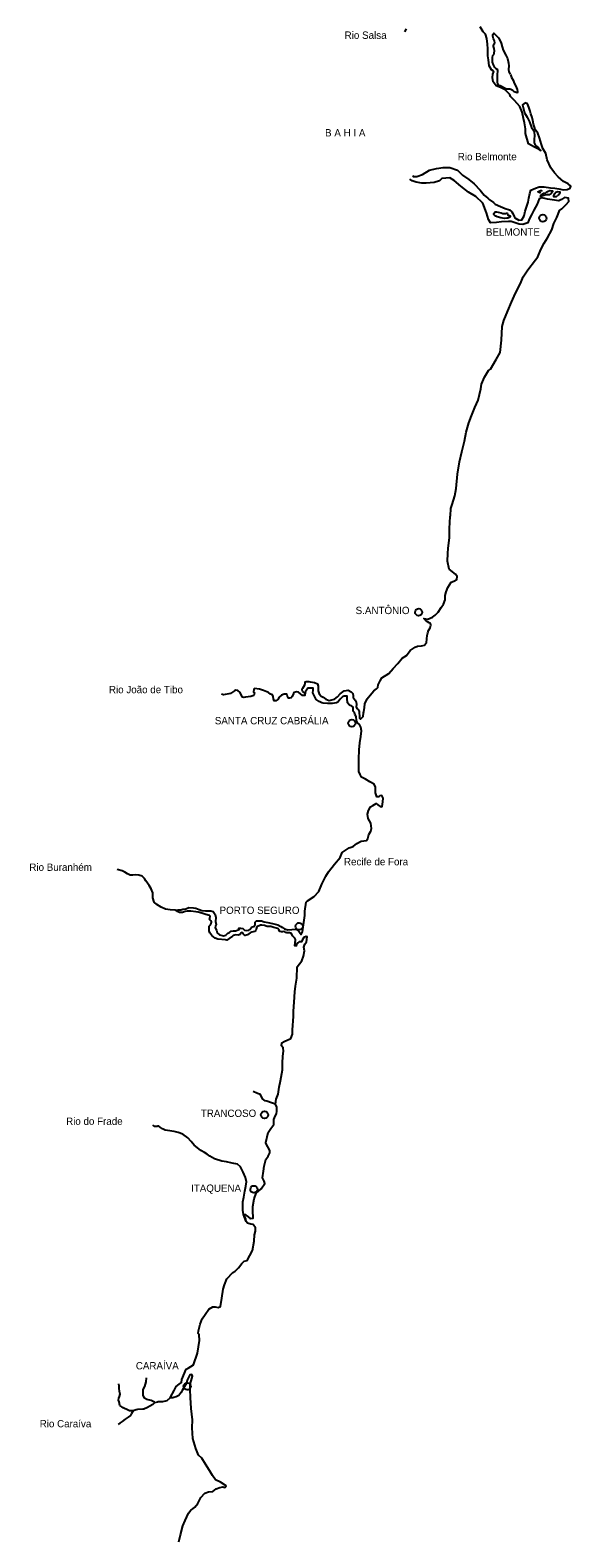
# Model space of a CAD drawing. Extents: x 662444 to 1640468, y 7452018 to 9606170.
# Drawn here: x 1109656 to 1158304, y 8117861 to 8253447 of the extents above; entities that cross this region are included whole.
import ezdxf

# ---------------------------------------------------------------- set-up
doc = ezdxf.new("R2010")
doc.units = 0
for name, color, linetype in [('Level 1', 7, 'Continuous'), ('Level 2', 7, 'Continuous'), ('Level 3', 7, 'Continuous')]:
    doc.layers.add(name, color=color, linetype=linetype)

msp = doc.modelspace()

# ---------------------------------------------------------------- linework, layer by layer
at = {"layer": 'Level 1'}
msp.add_line((1129077, 8146318), (1128864, 8146948), dxfattribs=at)
for points in [[(1143491, 8253560), (1143322, 8253309)], [(1151324, 8249799), (1151165, 8249881), (1150959, 8250243), (1150900, 8250790), (1150845, 8251125), (1150843, 8251437), (1150820, 8251760), (1150800, 8252194), (1150750, 8252685), (1150610, 8253079), (1150423, 8253307), (1150144, 8253737)], [(1152866, 8249465), (1152976, 8249184), (1153109, 8248946), (1153209, 8248676), (1153341, 8248406), (1153402, 8248259), (1153472, 8248101), (1153500, 8247945), (1153498, 8247867), (1153464, 8247824), (1153208, 8247898), (1153072, 8248024), (1152912, 8248106), (1152806, 8248154), (1152730, 8248145), (1152687, 8248146), (1152526, 8248151), (1152345, 8248245), (1152133, 8248352), (1151931, 8248435), (1151823, 8248438), (1151731, 8248597), (1151693, 8248787), (1151701, 8249054), (1151707, 8249254), (1151713, 8249487), (1151720, 8249721), (1151725, 8249876), (1151576, 8249970), (1151451, 8250084), (1151339, 8250321), (1151260, 8250579), (1151255, 8250780), (1151261, 8250980), (1151277, 8251157), (1151365, 8251244), (1151413, 8251387), (1151419, 8251598), (1151403, 8251810), (1151354, 8251967), (1151357, 8252078), (1151370, 8252134), (1151416, 8252232), (1151450, 8252309), (1151444, 8252487), (1151353, 8252668), (1151284, 8252892), (1151278, 8253071), (1151367, 8253179), (1151807, 8252744), (1152002, 8252382), (1152031, 8252270), (1152129, 8251956), (1152228, 8251653), (1152452, 8251201), (1152605, 8250896), (1152662, 8250628), (1152690, 8250482), (1152716, 8250248), (1152706, 8249915), (1152732, 8249691), (1152834, 8249499)], [(1144073, 8240363), (1144113, 8240284), (1144448, 8240297), (1144948, 8240461), (1145594, 8240854), (1146223, 8241002), (1146829, 8241096), (1147421, 8241090), (1148114, 8240848), (1148543, 8240402), (1149124, 8240007), (1149597, 8239637), (1150140, 8239054), (1150516, 8238620), (1150820, 8238333), (1150956, 8238207), (1151336, 8237940), (1151482, 8237802), (1151961, 8237577), (1152408, 8237408), (1152770, 8237287), (1153002, 8237113), (1153095, 8236954), (1153194, 8236685), (1153266, 8236560), (1153637, 8236371), (1153896, 8236386), (1154090, 8236747), (1154188, 8237167), (1154352, 8237619), (1154460, 8237971), (1154514, 8238348), (1154601, 8238746), (1154717, 8239043), (1155132, 8239231), (1155448, 8239367), (1155900, 8239353), (1156479, 8239281), (1156865, 8239225), (1157230, 8239170), (1157637, 8239080), (1157972, 8239126), (1158234, 8239252), (1158304, 8239416), (1158062, 8239613), (1157638, 8239848), (1157165, 8240262), (1156820, 8240617), (1156488, 8241061), (1156186, 8241781), (1156063, 8242341), (1155774, 8242795), (1155667, 8243165), (1155468, 8243749), (1155319, 8244176), (1155103, 8244516), (1155044, 8244729), (1154955, 8244988), (1154889, 8245312), (1154833, 8245603), (1154702, 8245919), (1154633, 8246154), (1154536, 8246513), (1154416, 8246817), (1154192, 8246924), (1153939, 8246720), (1154145, 8246024), (1154381, 8245616), (1154574, 8245210), (1154774, 8244693), (1154980, 8244386), (1155000, 8244308), (1155032, 8243940), (1155013, 8243651), (1155004, 8243329), (1155075, 8243182), (1155220, 8243011), (1155388, 8242850), (1155555, 8242656), (1155597, 8242611), (1155215, 8242833), (1155024, 8242917), (1154505, 8243221), (1154220, 8244164), (1154232, 8244586), (1154119, 8245123), (1154055, 8245515), (1153931, 8246075), (1153698, 8246582), (1153229, 8247118), (1152873, 8247485), (1152825, 8247675), (1152552, 8247928), (1152383, 8248066), (1151959, 8248279), (1151586, 8248434), (1151306, 8248798), (1151241, 8249178), (1151293, 8249488), (1151365, 8249720), (1151324, 8249799)], [(1156945, 8236419), (1157036, 8236594), (1157164, 8236902), (1157291, 8237221), (1157500, 8237371), (1157711, 8237576), (1157878, 8237771), (1158123, 8238031), (1158089, 8238344), (1157746, 8238409), (1157471, 8238206), (1157209, 8238091), (1156609, 8238187), (1156201, 8238243), (1156084, 8238269), (1155699, 8238369), (1155448, 8238276), (1155262, 8237803), (1154977, 8237244), (1154760, 8236828), (1154566, 8236444), (1154438, 8236114), (1153981, 8235972), (1153638, 8236004), (1152944, 8236225), (1152697, 8236232), (1152061, 8236206), (1151628, 8236152), (1151068, 8236124), (1150882, 8236407), (1150727, 8237012), (1150397, 8237878), (1149747, 8238476), (1149080, 8238884), (1148395, 8239405), (1147807, 8239922), (1147427, 8240167), (1146692, 8240099), (1146482, 8239905), (1145993, 8239741), (1145280, 8239673), (1144882, 8239684), (1144379, 8239776), (1144027, 8239909), (1143806, 8240060)], [(1155606, 8238861), (1155508, 8238831), (1155443, 8238833), (1155338, 8238903), (1155382, 8238946), (1155513, 8239009), (1155578, 8239018), (1155632, 8239027), (1155653, 8239016), (1155618, 8238905)], [(1156100, 8238814), (1156156, 8238901), (1156255, 8238976), (1156397, 8239027), (1156568, 8239000), (1156643, 8238987), (1156641, 8238909), (1156518, 8238757), (1156342, 8238651), (1156148, 8238645), (1155954, 8238618), (1155779, 8238545), (1155703, 8238514), (1155574, 8238506), (1155542, 8238529), (1155642, 8238627), (1155752, 8238701), (1155861, 8238776), (1156078, 8238814)], [(1157039, 8238530), (1156940, 8238444), (1156757, 8238449), (1156760, 8238572), (1156852, 8238758), (1156963, 8238877), (1157137, 8238928), (1157298, 8238912), (1157307, 8238856), (1157292, 8238712), (1157215, 8238658), (1157083, 8238562)], [(1151686, 8236651), (1151559, 8236721), (1151443, 8236813), (1151380, 8236882), (1151383, 8236971), (1151484, 8237101), (1151623, 8237097), (1151763, 8237093), (1152041, 8237019), (1152190, 8236970), (1152330, 8236966), (1152427, 8236963), (1152514, 8236982), (1152578, 8236981), (1152598, 8236924), (1152638, 8236823), (1152703, 8236810), (1152777, 8236775), (1152852, 8236761), (1152849, 8236661), (1152750, 8236586), (1152630, 8236545), (1152555, 8236547), (1152325, 8236514), (1152009, 8236567), (1151686, 8236651)], [(1139251, 8192075), (1139284, 8191729), (1139280, 8191585), (1139384, 8191470), (1139607, 8191731), (1139637, 8192041), (1139673, 8192152), (1139737, 8192528), (1139779, 8192849), (1139964, 8193300), (1140410, 8193832), (1140587, 8194027), (1140829, 8194209), (1140929, 8194328), (1140979, 8194571), (1141141, 8194945), (1141288, 8195196), (1141922, 8195578), (1142323, 8196045), (1142723, 8196489), (1143124, 8196967), (1143507, 8197200), (1143832, 8197658), (1144282, 8197967), (1144510, 8198060), (1144877, 8198094), (1145146, 8198131), (1145214, 8198251), (1145304, 8198360), (1145335, 8198703), (1145387, 8199002), (1145426, 8199235), (1145508, 8199466), (1145644, 8199696), (1145704, 8199927), (1145666, 8200073), (1145561, 8200154), (1145413, 8200247), (1145223, 8200375), (1145088, 8200524), (1145249, 8200519), (1145431, 8200480), (1145855, 8200657), (1146097, 8200850), (1146352, 8201121), (1146622, 8201524), (1146835, 8201830), (1146987, 8202214), (1146998, 8202603), (1147073, 8202946), (1147224, 8203331), (1147539, 8203800), (1147778, 8203904), (1148051, 8204052), (1148070, 8204329), (1147925, 8204512), (1147347, 8204963), (1147207, 8205690), (1147249, 8206378), (1147263, 8206856), (1147398, 8207787), (1147390, 8208621), (1147455, 8209709), (1147489, 8209775), (1147519, 8210430), (1147626, 8210794), (1147864, 8211555), (1147991, 8212219), (1148104, 8213528), (1148298, 8214612), (1148497, 8215530), (1148740, 8216491), (1148882, 8217299), (1149111, 8218126), (1149377, 8218764), (1149668, 8219523), (1149977, 8220170), (1150212, 8221197), (1150267, 8221619), (1150533, 8222245), (1150906, 8222846), (1151071, 8222974), (1151570, 8223839), (1151933, 8224462), (1152062, 8225582), (1152109, 8226793), (1152286, 8227333), (1152623, 8228191), (1152969, 8228982), (1153337, 8229794), (1153761, 8230661), (1154026, 8231254), (1154422, 8231887), (1155126, 8232790), (1155339, 8233073), (1155616, 8233710), (1155902, 8234291), (1156196, 8234761), (1156605, 8235483), (1156762, 8236046), (1156945, 8236419)], [(1138973, 8191738), (1138861, 8191942), (1138833, 8192087), (1138812, 8192110), (1138760, 8192167), (1138728, 8192190), (1138710, 8192291), (1138715, 8192458), (1138707, 8192569), (1138613, 8192650), (1138380, 8192757), (1138203, 8192962), (1138171, 8193341), (1138177, 8193541), (1138081, 8193555), (1137973, 8193558), (1137909, 8193549), (1137767, 8193486), (1137547, 8193293), (1137324, 8193021), (1137214, 8192958), (1136858, 8192879), (1136407, 8192892), (1136032, 8192936), (1135893, 8192952), (1135649, 8193059), (1135397, 8193266), (1135233, 8193549), (1135103, 8193853), (1135109, 8194087), (1135115, 8194276), (1135050, 8194277), (1134879, 8194282), (1134653, 8194267), (1134508, 8194104), (1134419, 8193984), (1134402, 8193796), (1134161, 8193992), (1134122, 8194126), (1134124, 8194204), (1134180, 8194281), (1134382, 8194575), (1134387, 8194731), (1134401, 8194852), (1134477, 8194872), (1134724, 8194865), (1134852, 8194828), (1135055, 8194800), (1135248, 8194794), (1135513, 8194653), (1135582, 8194462), (1135576, 8194262), (1135570, 8194029), (1135659, 8193770), (1135835, 8193565), (1136015, 8193449), (1136257, 8193275), (1136555, 8193177), (1137042, 8193296), (1137316, 8193500), (1137550, 8193771), (1137923, 8194027), (1138257, 8194084), (1138543, 8193931), (1138690, 8193804), (1138715, 8193581), (1138733, 8193447), (1138909, 8193208), (1139000, 8193017), (1139005, 8192816), (1138998, 8192605), (1139036, 8192437), (1139205, 8192332), (1139267, 8192230), (1139251, 8192075)], [(1134402, 8193796), (1134379, 8193730), (1134365, 8193619), (1134161, 8193614), (1133983, 8193764), (1133804, 8193902), (1133633, 8193929), (1133417, 8193891), (1133350, 8193793), (1133234, 8193529), (1133134, 8193399), (1132983, 8193370), (1132886, 8193373), (1132786, 8193609), (1132746, 8193722), (1132510, 8193728), (1132271, 8193635), (1132051, 8193464), (1131937, 8193245), (1131762, 8193138), (1131622, 8193142), (1131541, 8193301), (1131526, 8193523), (1131455, 8193670), (1131285, 8193719), (1131107, 8193891), (1130661, 8194060), (1130277, 8194182), (1129838, 8194228), (1129783, 8194185), (1129754, 8193919), (1129827, 8193839), (1129767, 8193608), (1129518, 8193537), (1129043, 8193473), (1128881, 8193444), (1128753, 8193470), (1128610, 8193741), (1128550, 8193876), (1128351, 8194060), (1128148, 8194088), (1128039, 8194047), (1127688, 8193790), (1127040, 8193675), (1126870, 8193724)], [(1133192, 8172566), (1133547, 8172612), (1133821, 8172426), (1133882, 8172335), (1134037, 8172119), (1134162, 8172349), (1134367, 8173833), (1134378, 8174233), (1134477, 8175031), (1134620, 8175138), (1135200, 8175533), (1135632, 8175976), (1135899, 8176658), (1136263, 8177359), (1136500, 8177741), (1137047, 8178459), (1137537, 8179056), (1137743, 8179484), (1138346, 8179900), (1138704, 8180023), (1139045, 8180291), (1139438, 8180524), (1139912, 8180577), (1140046, 8180740), (1140121, 8181105), (1140302, 8181411), (1140363, 8181665), (1140301, 8182123), (1140067, 8182563), (1140014, 8182943), (1140110, 8183274), (1140270, 8183592), (1140488, 8183708), (1140773, 8183899), (1140941, 8183772), (1141141, 8183633), (1141290, 8183595), (1141323, 8183638), (1141378, 8184037), (1141421, 8184381), (1141309, 8184607), (1141115, 8184579), (1141027, 8184504), (1140855, 8184498), (1140726, 8184857), (1140740, 8185357), (1140609, 8185639), (1140207, 8185840), (1139817, 8186085), (1139479, 8186273), (1139346, 8186511), (1139214, 8186782), (1139220, 8187360), (1139236, 8187882), (1139260, 8188716), (1139322, 8189370), (1139414, 8189912), (1139461, 8190423), (1139396, 8190780), (1139274, 8191018), (1139117, 8191167), (1139026, 8191359), (1138973, 8191738)], [(1122745, 8174294), (1122243, 8174353), (1121836, 8174387), (1121455, 8174587), (1121043, 8174810), (1120824, 8175039), (1120707, 8175420), (1120687, 8175854), (1120558, 8176236), (1120352, 8176520), (1120053, 8176940), (1119951, 8177143), (1119743, 8177360), (1119434, 8177469), (1119145, 8177478), (1118897, 8177451), (1118651, 8177458), (1118428, 8177565), (1118186, 8177739), (1117932, 8177857), (1117484, 8177959)], [(1129827, 8172398), (1129611, 8172338), (1129459, 8172275), (1129206, 8172083), (1129012, 8172044), (1128906, 8172080), (1128823, 8172172), (1128794, 8172284), (1128686, 8172287), (1128632, 8172255), (1128553, 8172135), (1128542, 8172124), (1128380, 8172073), (1128176, 8172079), (1127928, 8172031), (1127851, 8171966), (1127566, 8171775), (1127347, 8171625), (1127218, 8171629), (1126544, 8171693), (1126311, 8171800), (1126017, 8172020), (1125832, 8172281), (1125761, 8172450), (1125768, 8172672), (1125773, 8172861), (1125874, 8173003), (1125953, 8173123), (1125967, 8173244), (1125916, 8173335), (1125791, 8173483), (1125837, 8173571), (1125842, 8173760), (1125801, 8173828), (1125460, 8173915), (1125110, 8174037), (1124769, 8174124), (1124577, 8174163), (1124106, 8174221), (1123785, 8174231), (1123612, 8174202), (1123362, 8174087), (1123083, 8174095), (1122914, 8174200), (1122745, 8174294), (1122972, 8174332), (1123218, 8174325), (1123403, 8174386), (1123651, 8174435), (1123933, 8174538), (1124362, 8174525), (1124565, 8174486), (1124861, 8174355), (1125106, 8174281), (1125438, 8174261), (1125910, 8174247), (1126133, 8174174), (1126298, 8173924), (1126354, 8173656), (1126343, 8173278), (1126379, 8173032), (1126343, 8172900), (1126306, 8172734), (1126418, 8172509), (1126497, 8172273), (1126696, 8172100), (1127047, 8172012), (1127263, 8172061), (1127429, 8172234), (1127582, 8172308), (1127746, 8172414), (1127940, 8172453), (1128144, 8172458), (1128459, 8172571), (1128428, 8172639), (1128419, 8172684), (1128612, 8172678), (1128805, 8172673), (1128888, 8172581), (1128950, 8172502), (1129132, 8172474), (1129326, 8172502), (1129435, 8172576), (1129580, 8172761), (1129667, 8172803), (1129841, 8172865), (1129898, 8172985), (1129902, 8173108), (1129916, 8173218), (1130026, 8173338), (1130295, 8173341), (1130466, 8173336), (1130722, 8173273), (1131042, 8173186), (1131447, 8173096), (1131927, 8172982), (1132223, 8172840), (1132349, 8172758), (1132528, 8172619), (1132826, 8172533), (1133192, 8172566)], [(1129077, 8146318), (1129057, 8146511), (1128940, 8146812), (1128915, 8146946), (1129035, 8146931), (1129161, 8146828), (1129411, 8146598), (1129507, 8146573), (1129712, 8146622), (1129679, 8147313), (1129690, 8147668), (1129817, 8148343), (1130003, 8148849), (1130434, 8149259), (1130769, 8149716), (1130722, 8149929), (1130559, 8150223), (1130641, 8150832), (1130708, 8151297), (1130865, 8151893), (1131067, 8152176), (1131216, 8152494), (1131222, 8152694), (1130866, 8153350), (1130847, 8153428), (1131066, 8154312), (1131301, 8154661), (1131581, 8155042), (1131593, 8155475), (1131710, 8155794), (1131824, 8156002), (1131852, 8156235), (1131841, 8156580), (1131731, 8156850), (1131787, 8157315), (1131972, 8157766), (1132055, 8158386), (1132190, 8158961), (1132359, 8159957), (1132365, 8160535), (1132384, 8161168), (1132440, 8161634), (1132406, 8161935), (1132282, 8162094), (1132291, 8162372), (1132509, 8162488), (1133117, 8162759), (1133258, 8163144), (1133269, 8163544), (1133337, 8164743), (1133362, 8165232), (1133407, 8166043), (1133478, 8166975), (1133535, 8167474), (1133578, 8167828), (1133653, 8168182), (1133672, 8169205), (1134085, 8169749), (1134259, 8170177), (1134326, 8170642), (1134283, 8170977), (1134366, 8171253), (1134512, 8171471), (1134567, 8171903), (1134494, 8171950), (1134287, 8171845), (1134140, 8171615), (1134060, 8171451), (1133996, 8171453), (1133846, 8171468)], [(1133846, 8171468), (1133746, 8171349), (1133671, 8171351), (1133601, 8171164), (1133620, 8171086), (1133567, 8171087), (1133482, 8171112), (1133483, 8171168), (1133498, 8171301), (1133502, 8171434), (1133517, 8171589), (1133519, 8171656), (1133480, 8171779), (1133365, 8171894), (1133272, 8172008), (1133170, 8172211), (1133000, 8172261), (1132829, 8172266), (1132764, 8172268), (1132647, 8172293), (1132584, 8172351), (1132478, 8172376), (1132370, 8172357), (1132263, 8172360), (1132134, 8172386), (1132032, 8172545), (1131928, 8172670), (1131577, 8172758), (1131310, 8172833), (1130989, 8172842), (1130755, 8172916), (1130509, 8172945), (1130370, 8172972), (1130043, 8172803), (1129994, 8172593), (1129969, 8172472), (1129827, 8172398)], [(1131731, 8156850), (1131370, 8156972), (1130956, 8157129), (1130796, 8157156), (1130555, 8157352), (1130395, 8157735), (1130118, 8157810), (1129716, 8157988)], [(1128864, 8146948), (1128779, 8147319), (1128780, 8148073), (1128867, 8148504), (1128980, 8149035), (1129047, 8149489), (1129123, 8149887), (1129027, 8150268), (1128827, 8150752), (1128573, 8151238), (1128323, 8151479), (1127832, 8151549), (1127310, 8151664), (1126894, 8151743), (1126246, 8151940), (1125834, 8152175), (1125593, 8152360), (1125341, 8152523), (1125013, 8152688), (1124689, 8152965), (1124427, 8153184), (1124147, 8153503), (1123846, 8153846), (1123384, 8154170), (1122981, 8154327), (1122618, 8154393), (1122021, 8154499), (1121818, 8154528), (1121575, 8154635), (1121396, 8154762), (1121228, 8154889), (1121153, 8154892), (1121077, 8154849), (1120991, 8154841), (1120873, 8154844), (1120705, 8154960)], [(1129828, 8145106), (1129934, 8145437), (1129944, 8145748), (1129717, 8146044), (1129524, 8146072), (1129216, 8146159), (1129077, 8146318)], [(1123030, 8117506), (1123177, 8118135), (1123383, 8118941), (1123601, 8119435), (1123899, 8120071), (1124121, 8120353), (1124307, 8120481), (1124482, 8120610), (1124728, 8120958), (1125022, 8121494), (1125387, 8121884), (1125701, 8121997), (1126088, 8122041), (1126384, 8122265), (1126719, 8122378), (1126978, 8122437), (1127180, 8122397), (1127292, 8122550), (1126787, 8122876), (1126333, 8123079), (1126056, 8123476), (1125802, 8123929), (1125433, 8124485), (1125096, 8125040), (1124815, 8125304), (1124565, 8125901), (1124281, 8126810), (1124234, 8127756), (1124255, 8128468), (1124146, 8129483), (1124080, 8130486), (1124048, 8131209), (1124061, 8131676), (1124146, 8131996), (1124265, 8132415), (1124206, 8132561), (1124022, 8132522), (1123794, 8132040), (1123732, 8131775), (1123531, 8131469), (1123327, 8131108), (1123213, 8130889), (1123025, 8130661), (1122786, 8130546), (1122569, 8130475), (1122504, 8130454), (1122429, 8130457), (1122258, 8130462), (1122292, 8130527), (1122599, 8131108), (1122802, 8131469), (1123066, 8131694), (1123262, 8131822), (1123302, 8132088), (1123684, 8133033), (1123879, 8133116), (1124359, 8133413), (1124701, 8134460), (1124885, 8135600), (1124868, 8136112), (1124775, 8136226), (1124804, 8136481), (1124939, 8137077), (1125146, 8137560), (1125404, 8137953), (1125740, 8138432), (1126089, 8138633), (1126292, 8138627), (1126558, 8138564), (1126797, 8138679), (1126894, 8139410), (1127025, 8140229), (1127144, 8140615), (1127353, 8141154), (1127895, 8141716), (1128102, 8141832), (1128411, 8142134), (1128691, 8142538), (1128911, 8142731), (1129181, 8142790), (1129647, 8143710), (1129801, 8144551), (1129828, 8145106)], [(1122258, 8130462), (1121961, 8130181), (1121573, 8130093), (1121187, 8130082), (1121100, 8130062), (1120852, 8129992), (1120687, 8129841), (1120415, 8129693), (1120229, 8129576), (1119893, 8129442), (1119786, 8129434), (1119324, 8129392), (1119184, 8129363), (1118925, 8129270), (1118593, 8129280), (1118477, 8129339), (1118034, 8129563), (1117907, 8129645), (1117718, 8129762), (1117664, 8130097), (1117604, 8130254), (1117630, 8130409), (1117688, 8130563), (1117748, 8130795), (1117702, 8131030), (1117656, 8131309), (1117662, 8131498), (1117636, 8131721)], [(1120852, 8129992), (1120833, 8130070), (1120537, 8130212), (1120154, 8130301), (1119944, 8130430), (1119823, 8130700), (1119832, 8130989), (1119838, 8131200), (1119974, 8131463), (1120084, 8131905), (1120115, 8132249)], [(1118925, 8129270), (1118779, 8129041), (1118677, 8128877), (1118469, 8128728), (1118218, 8128535), (1117933, 8128332), (1117747, 8128204), (1117572, 8128065)]]:
    msp.add_lwpolyline(points, dxfattribs=at)
at = {"layer": 'Level 2'}
for centre, major_axis, ratio in [((1155785, 8236542), (323, -9), 0.9999973), ((1144610, 8201105), (322, -9), 0.9999974), ((1138601, 8191126), (322, -9), 0.9999974), ((1133858, 8172857), (322, -10), 0.9999974), ((1130737, 8155901), (321, -10), 0.9999974), ((1129789, 8149211), (321, -10), 0.9999974), ((1123788, 8131484), (321, -10), 0.9999974)]:
    msp.add_ellipse(centre, major_axis=major_axis, ratio=ratio, dxfattribs=at)

# ---------------------------------------------------------------- texts
at = {"layer": 'Level 3'}
for s, height, p in [('Rio Salsa', 661, (1137945, 8252666)), ('B A H I A', 660.7, (1136188, 8243888)), ('Rio Belmonte', 660.78, (1148129, 8241748)), ('BELMONTE', 660.6, (1150660, 8234966)), ('S.ANTÔNIO', 659.5, (1138939, 8200933)), ('Rio João de Tibo', 659.02, (1116743, 8193818)), ('SANTA CRUZ CABRÁLIA', 659.05, (1126270, 8191021)), ('Recife de Fora', 658.79, (1137888, 8178340)), ('Rio Buranhém', 658.44, (1109584, 8177845)), ('PORTO SEGURO', 658.52, (1126698, 8173969)), ('Rio do Frade', 657.79, (1112893, 8155000)), ('TRANCOSO', 657.9, (1125012, 8155715)), ('ITAQUENA', 657.7, (1124137, 8148978)), ('CARAÍVA', 657.2, (1119166, 8133009)), ('Rio Caraíva', 656.92, (1110518, 8127799))]:
    msp.add_text(s, height=height, dxfattribs=at).set_placement(p)

doc.saveas('drawing.dxf')
